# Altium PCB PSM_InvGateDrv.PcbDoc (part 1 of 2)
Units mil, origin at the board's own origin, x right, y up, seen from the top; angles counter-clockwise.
Board outline 5413.39 x 1771.65 mil, 2 copper layers (Top Layer, Bottom Layer), stack 62 mil thick; 130 components, 58 nets, 317 pads, 172 vias.
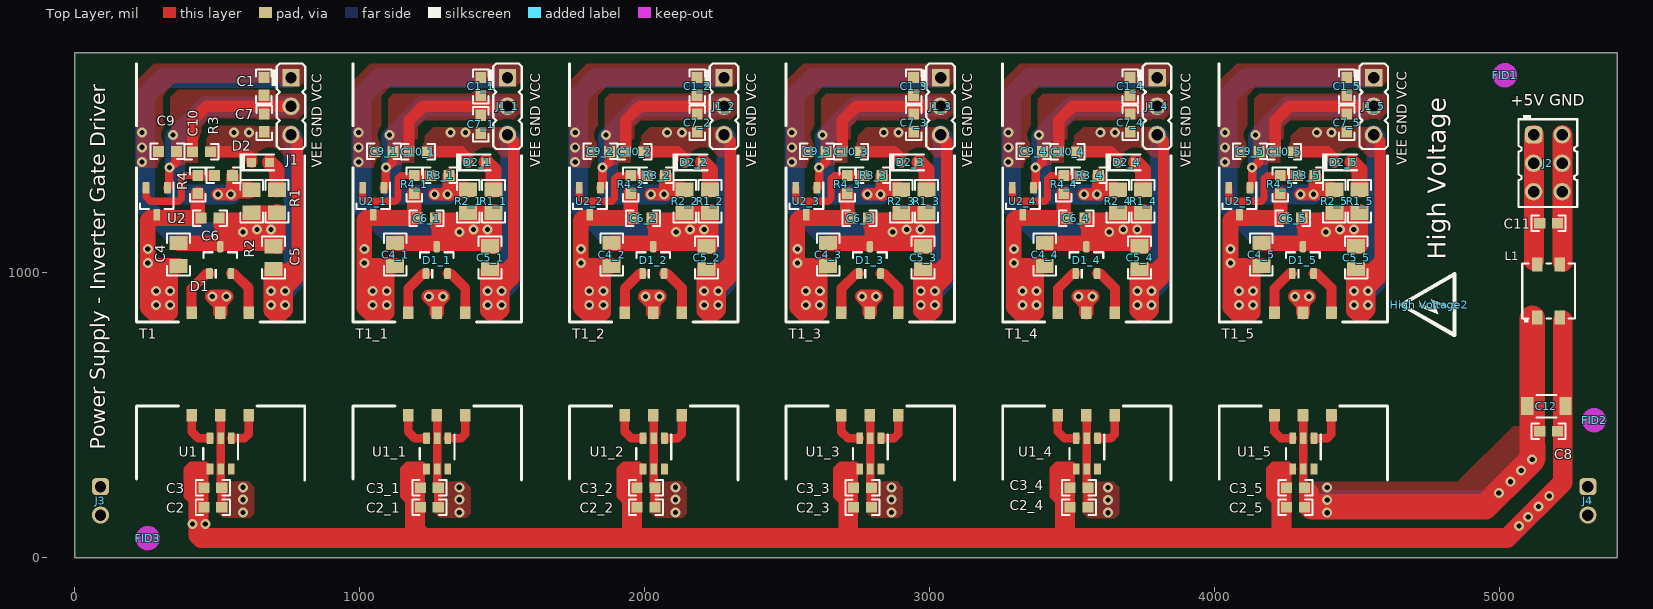
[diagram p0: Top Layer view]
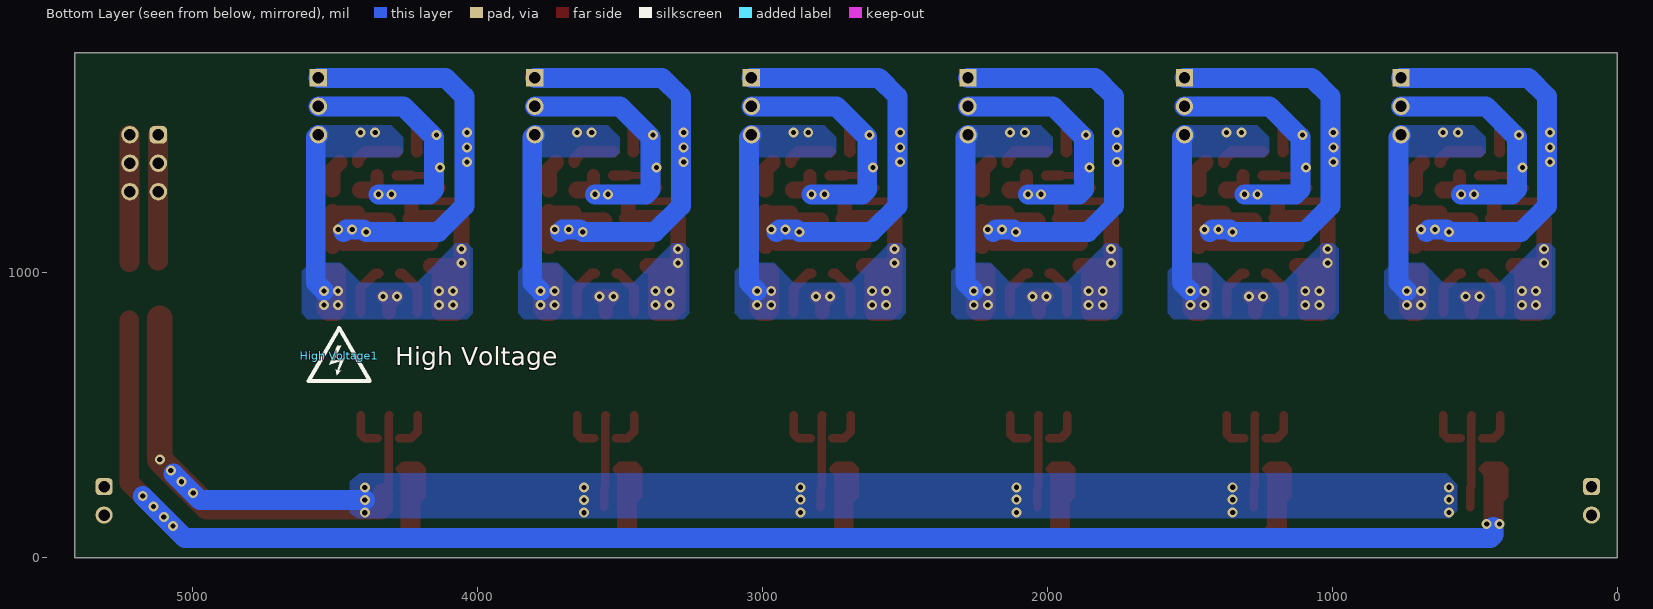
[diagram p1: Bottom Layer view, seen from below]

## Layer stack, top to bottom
Top Solder: solder mask 0.4, Solder Resist, Dk 3.5
Top Layer: signal copper 1.4
Dielectric1: core 59.2, FR-4, Dk 4.8
Bottom Layer: signal copper 1.4
Bottom Solder: solder mask 0.4, Solder Resist, Dk 3.5

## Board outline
0,0 5413.39,0 5413.39,1771.65 0,1771.65

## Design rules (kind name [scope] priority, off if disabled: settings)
AcuteAngle [All] p1: minimum=4.50000000000000E+0001 checktracksonly=FALSE
AssemblyTestPointUsage [All] p1: valid=2
BoardOutlineClearance BoardOutlineClearance_MountingHoles [OnCopper and InComponentClass('Mounting Holes')] p1: gap=20 ignorepadtopadclearanceinfootprint=FALSE
BoardOutlineClearance BoardOutlineClearance_Poly [OnCopper and IsPoly] p2: gap=25 ignorepadtopadclearanceinfootprint=FALSE
BoardOutlineClearance [OnCopper and Not InComponentClass('Logo') and not InComponentClass('FiducialMark') and not InRegion(1000,500,4000,800) and not InPoly] p3: gap=20 ignorepadtopadclearanceinfootprint=FALSE
Clearance Clearance_Keepouts [((IsTrack Or IsArc) And Not InPoly) And IsFree and IsKeepOut vs ((IsTrack Or IsArc) And Not InPoly) And IsFree and IsKeepOut] p1: gap=0 ignorepadtopadclearanceinfootprint=FALSE
Clearance Clearance_Poly [InPolygon] p2: gap=25 ignorepadtopadclearanceinfootprint=TRUE
Clearance Clearance_FiducialMark [IsKeepOut and InComponentClass('FiducialMark') vs IsPad and InComponentClass('FiducialMark')] p3: gap=0 ignorepadtopadclearanceinfootprint=FALSE
Clearance [All] p4: gap=7.87 ignorepadtopadclearanceinfootprint=TRUE
ComponentClearance ComponentClearance_MountingHoles_FiducialMarks [InComponentClass('Mounting Holes') vs InComponentClass('FiducialMark')] p1: gap=50 collisioncheckmode=3 verticalgap=10 showdistances=FALSE
ComponentClearance ComponentClearance_Shunt [InComponentClass('Header') vs InComponentClass('Shunt')] p2: gap=0 collisioncheckmode=3 verticalgap=0 showdistances=FALSE
ComponentClearance ComponentClearance_Logo [InComponentClass('Logo')] p3: gap=50 collisioncheckmode=3 verticalgap=10 showdistances=FALSE
ComponentClearance ComponentClearance_ScrewToNut [(HasFootprint('NY PMS 440 0025 PH')) vs (HasFootprint('Keystone_1902C'))] p4: gap=5 collisioncheckmode=3 verticalgap=10 showdistances=FALSE
ComponentClearance ComponentClearance_MountingHoles [InComponentClass('Mounting Holes')] p5: gap=250 collisioncheckmode=3 verticalgap=100000 showdistances=FALSE
ComponentClearance ComponentClearance_SmallPassives [HasFootprint('0201*') or HasFootprint('0402*') or HasFootprint('0508') or HasFootprint('0603*') or HasFootprint('0612') or HasFootprint('0805*') or HasFootprint('0815*') or HasFootprint('0830*') or HasFootprint('1206*') or HasFootprint('1210*') or HasFootprint('1808*') or HasFootprint('1812*') or HasFootprint('1825*') or HasFootprint('2010*') or HasFootprint('2220*') or HasFootprint('2225*') or HasFootprint('2512*') or HasFootprint('2728*') or HasFootprint('3518*') vs HasFootprint('0201*') or HasFootprint('0402*') or HasFootprint('0508') or HasFootprint('0603*') or HasFootprint('0612') or HasFootprint('0805*') or HasFootprint('0815*') or HasFootprint('0830*') or HasFootprint('1206*') or HasFootprint('1210*') or HasFootprint('1808*') or HasFootprint('1812*') or HasFootprint('1825*') or HasFootprint('2010*') or HasFootprint('2220*') or HasFootprint('2225*') or HasFootprint('2512*') or HasFootprint('2728*') or HasFootprint('3518*')] p6: gap=14.96 collisioncheckmode=3 verticalgap=10 showdistances=FALSE
ComponentClearance ComponentClearance_THtoSMT [IsThruComponent vs IsSMTComponent] p7: gap=25 collisioncheckmode=3 verticalgap=30 showdistances=FALSE
ComponentClearance ComponentClearance_THtoTH [IsThruComponent vs IsThruComponent] p8: gap=30 collisioncheckmode=3 verticalgap=30 showdistances=FALSE
ComponentClearance [All] p9: gap=30 collisioncheckmode=3 verticalgap=10 showdistances=FALSE
DiffPairsRouting [All] p1: maxlimit=100 minlimit=10 mostfreqgap=10 toplayer_minwidth=15 toplayer_maxwidth=15 toplayer_prefwidth=15 bottomlayer_minwidth=15 bottomlayer_maxwidth=15 bottomlayer_prefwidth=15 maxuncoupledlength=1000
FabricationTestPointUsage TestPointUsage [All] p1: valid=2 allowmultiple=FALSE
FabricationTestpoint Testpoint [All] p1: side=3 testpointundercomponent=TRUE minsize=40 maxsize=100 preferedsize=60 minholesize=0 maxholesize=40 preferedholesize=32 testpointgrid=1 allowsidetop=TRUE allowsidebottom=TRUE usegrid=TRUE gridtolerance=0.01
FanoutControl Fanout_LCC [IsLCC] p1: bgadir=Out bgaviamode=Centered fanoutstyle=Auto fanoutdirection=Alternating viagrid=1 // Fanout_LCC (Default Rule)
FanoutControl Fanout_BGA [IsBGA] p2: bgadir=Out bgaviamode=Centered fanoutstyle=Auto fanoutdirection=Alternating viagrid=1 // Fanout_BGA (Default Rule)
FanoutControl Fanout_Default [All] p4: bgadir=Out bgaviamode=Centered fanoutstyle=Auto fanoutdirection=Alternating viagrid=1 // Fanout_Default (Default Rule)
FanoutControl Fanout_Small [(CompPinCount < 5)] p5: bgadir=Out bgaviamode=Centered fanoutstyle=Auto fanoutdirection=OutThenIn viagrid=1 // Fanout_Small (Default Rule)
HoleSize [All] p1: absolutevalues=TRUE maxlimit=251 minlimit=7.87 maxpercent=80.000 minpercent=20.000
MinimumAnnularRing MinimumAnnularRing_ThermalPadVias [IsVia and InAnyComponent] p1: minimumring=5.91
MinimumAnnularRing [All] p2: minimumring=7.87
MinimumSolderMaskSliver MinimumSolderMaskSliver_Logo [InComponentClass('Logo') vs InComponentClass('Logo')] p1: minsoldermaskwidth=0.7
MinimumSolderMaskSliver [All] p2: minsoldermaskwidth=3.94
PlaneConnect [All] p1: planeconnectstyle=Relief reliefexpansion=10 reliefentries=4 reliefconductorwidth=10 reliefairgap=10
PolygonConnect [All] p1: connectstyle=Direct reliefconductorwidth=10 reliefentries=4 polygonreliefangle="90 Angle" airgapwidth=10
RoomDefinition "Bias Supply_4" [InComponentClass('Bias Supply')] p1: confinementstyle=ConfineIn formatcopy=TRUE lockcomponents=FALSE outline 4615.87,338.9 4615.87,1735.5 4015.87,1735.5 4015.87,338.9
RoomDefinition "Bias Supply_3" [InComponentClass('Bias Supply')] p2: confinementstyle=ConfineIn formatcopy=TRUE lockcomponents=FALSE outline 3855.87,338.9 3855.87,1735.5 3255.87,1735.5 3255.87,338.9
RoomDefinition "Bias Supply_2" [InComponentClass('Bias Supply')] p3: confinementstyle=ConfineIn formatcopy=TRUE lockcomponents=FALSE outline 3095.87,338.9 3095.87,1735.5 2495.87,1735.5 2495.87,338.9
RoomDefinition "Bias Supply_1" [InComponentClass('Bias Supply')] p4: confinementstyle=ConfineIn formatcopy=TRUE lockcomponents=FALSE outline 2335.87,338.9 2335.87,1735.5 1735.87,1735.5 1735.87,338.9
RoomDefinition 1 [InComponentClass('1')] p5: confinementstyle=ConfineIn formatcopy=TRUE lockcomponents=FALSE outline 4615.87,338.9 4615.87,1735.5 4015.87,1735.5 4015.87,338.9
RoomDefinition 2 [InComponentClass('2')] p6: confinementstyle=ConfineIn formatcopy=TRUE lockcomponents=FALSE outline 3855.87,338.9 3855.87,1735.5 3255.87,1735.5 3255.87,338.9
RoomDefinition 3 [InComponentClass('3')] p7: confinementstyle=ConfineIn formatcopy=TRUE lockcomponents=FALSE outline 3095.87,338.9 3095.87,1735.5 2495.87,1735.5 2495.87,338.9
RoomDefinition "Stark Gate Driver_1" [InComponentClass('Stark Gate Driver_1')] p8: confinementstyle=ConfineIn formatcopy=TRUE lockcomponents=FALSE outline 2335.87,338.9 2335.87,1735.5 1735.87,1735.5 1735.87,338.9
RoomDefinition "Bias Supply" [InComponentClass('Bias Supply')] p9: confinementstyle=ConfineIn formatcopy=TRUE lockcomponents=FALSE outline 815.87,338.9 815.87,1735.5 215.87,1735.5 215.87,338.9
RoomDefinition 5 [InComponentClass('5')] p10: confinementstyle=ConfineIn formatcopy=TRUE lockcomponents=FALSE outline 1575.87,338.9 1575.87,1735.5 975.87,1735.5 975.87,338.9
RoutingVias ThermalPadVias [IsVia and InAnyComponent] p1: holewidth=7.87 width=19.68 viastyle="Through Hole" minholewidth=7.87 minwidth=19.68 maxholewidth=12.99 maxwidth=23.62
RoutingVias [All] p2: holewidth=16 width=34 viastyle="Through Hole" minholewidth=7.87 minwidth=26 maxholewidth=40 maxwidth=65
SilkToBoardRegionClearance [Not ((IsComment or IsDesignator) And (Hide <> 'False')) and not InRegion(1000,500,4000,800)] p1:
SilkToSilkClearance SilkToSilkClearance_Pb-FreeLogo [(HasFootprint('Pb-Free_Overlay_Medium') OR HasFootprint('Pb-Free_Overlay_Small')) vs (HasFootprint('Pb-Free_Overlay_Medium') OR HasFootprint('Pb-Free_Overlay_Small'))] p1: silktosilkclearance=0
SilkToSilkClearance [All] p2: silktosilkclearance=2
SilkToSolderMaskClearance SilkToComponentPadClearance [(IsPad or IsFill or IsRegion) and InAnycomponent] p1: minsilkscreentomaskgap=0 clearancetoexposedcopper=TRUE
SilkToSolderMaskClearance "Silk to Solder Mask Opening" [All] p2: minsilkscreentomaskgap=1 clearancetoexposedcopper=FALSE
SolderMaskExpansion [All] p1: expansion=1.97
UnRoutedNet [All] p1: checkbadconnections=TRUE
Width [All] p1: maxlimit=100 minlimit=6 preferedwidth=10 checkconnectedcopper=TRUE
14 further rules are at their usual default settings.

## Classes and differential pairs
component class Header: J1 J1_1 J1_2 J1_3 J1_4 J1_5 J2 J3 J4
component class "Bias Supply": C1 C1_1 C1_2 C1_3 C1_4 C1_5 C2 C2_1 C2_2 C2_3 C2_4 C2_5 C3 C3_1 C3_2 C3_3 C3_4 C3_5 C4 C4_1 C4_2 C4_3 C4_4 C4_5 C5 C5_1 C5_2 C5_3 C5_4 C5_5 C6 C6_1 C6_2 C6_3 C6_4 C6_5 C7 C7_1 C7_2 C7_3 C7_4 C7_5 C8 C9 C9_1 C9_2 C9_3 C9_4 C9_5 C10 C10_1 C10_2 C10_3 C10_4 C10_5 C11 C12 D1 D1_1 D1_2 D1_3 D1_4 D1_5 D2 D2_1 D2_2 D2_3 D2_4 D2_5 J1 J1_1 J1_2 J1_3 J1_4 J1_5 J2 J3 J4 L1 R1 R1_1 R1_2 R1_3 R1_4 R1_5 R2 R2_1 R2_2 R2_3 R2_4 R2_5 R3 R3_1 R3_2 R3_3 R3_4 R3_5 R4 R4_1 R4_2 R4_3 R4_4 R4_5 T1 T1_1 T1_2 T1_3 T1_4 T1_5 U1 U1_1 U1_2 U1_3 U1_4 U1_5 U2 U2_1 U2_2 U2_3 U2_4 U2_5
component class Hardware: FID1 FID2 FID3 "High Voltage1" "High Voltage2" ZZ1 ZZ2 ZZ3 ZZ4
component class FiducialMark: FID1 FID2 FID3
component class AssemblyNote: ZZ1 ZZ2 ZZ3 ZZ4

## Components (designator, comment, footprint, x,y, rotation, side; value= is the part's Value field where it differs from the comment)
C1 "CGA3E2X7R1E104K080AA" 0603 663.75,1653.91 r270 top value=0.1uF
C1_1 "CGA3E2X7R1E104K080AA" 0603 1424.5,1653.54 r270 top value=0.1uF
C1_2 "CGA3E2X7R1E104K080AA" 0603 2183.75,1653.91 r270 top value=0.1uF
C1_3 "CGA3E2X7R1E104K080AA" 0603 2943.75,1653.91 r270 top value=0.1uF
C1_4 "CGA3E2X7R1E104K080AA" 0603 3703.75,1653.91 r270 top value=0.1uF
C1_5 "CGA3E2X7R1E104K080AA" 0603 4463.75,1653.91 r270 top value=0.1uF
C2 "GRT188C81A106ME13D" 0603 484.38,176.52 r180 top value=10uF
C2_1 "GRT188C81A106ME13D" 0603 1244.38,176.52 r180 top value=10uF
C2_2 "GRT188C81A106ME13D" 0603 2004.38,176.52 r180 top value=10uF
C2_3 "GRT188C81A106ME13D" 0603 2764.38,176.52 r180 top value=10uF
C2_4 "GRT188C81A106ME13D" 0603 3524.38,176.52 r180 top value=10uF
C2_5 "GRT188C81A106ME13D" 0603 4284.38,176.52 r180 top value=10uF
C3 "CGA3E2X7R1E104K080AA" 0603 484.38,245.42 r180 top value=0.1uF
C3_1 "CGA3E2X7R1E104K080AA" 0603 1244.38,245.42 r180 top value=0.1uF
C3_2 "CGA3E2X7R1E104K080AA" 0603 2004.38,245.42 r180 top value=0.1uF
C3_3 "CGA3E2X7R1E104K080AA" 0603 2764.38,245.42 r180 top value=0.1uF
C3_4 "CGA3E2X7R1E104K080AA" 0603 3524.38,245.42 r180 top value=0.1uF
C3_5 "CGA3E2X7R1E104K080AA" 0603 4284.38,245.42 r180 top value=0.1uF
C4 "GRT21BR61H475KE13L" 0805_HV 364.3,1063.78 r270 top value=4.7uF
C4_1 "GRT21BR61H475KE13L" 0805_HV 1124.3,1063.78 r270 top value=4.7uF
C4_2 "GRT21BR61H475KE13L" 0805_HV 1884.3,1063.78 r270 top value=4.7uF
C4_3 "GRT21BR61H475KE13L" 0805_HV 2644.3,1063.78 r270 top value=4.7uF
C4_4 "GRT21BR61H475KE13L" 0805_HV 3404.3,1063.78 r270 top value=4.7uF
C4_5 "GRT21BR61H475KE13L" 0805_HV 4164.3,1063.78 r270 top value=4.7uF
C5 "GRT21BR61H475KE13L" 0805_HV 697.3,1053.15 r270 top value=4.7uF
C5_1 "GRT21BR61H475KE13L" 0805_HV 1457.3,1053.15 r270 top value=4.7uF
C5_2 "GRT21BR61H475KE13L" 0805_HV 2217.3,1053.15 r270 top value=4.7uF
C5_3 "GRT21BR61H475KE13L" 0805_HV 2977.3,1053.15 r270 top value=4.7uF
C5_4 "GRT21BR61H475KE13L" 0805_HV 3737.3,1053.15 r270 top value=4.7uF
C5_5 "GRT21BR61H475KE13L" 0805_HV 4497.3,1053.15 r270 top value=4.7uF
C6 "CGA3E2X7R1E104K080AA" 0603 474.54,1191.73 r180 top value=0.1uF
C6_1 "CGA3E2X7R1E104K080AA" 0603 1234.54,1191.73 r180 top value=0.1uF
C6_2 "CGA3E2X7R1E104K080AA" 0603 1994.54,1191.73 r180 top value=0.1uF
C6_3 "CGA3E2X7R1E104K080AA" 0603 2754.54,1191.73 r180 top value=0.1uF
C6_4 "CGA3E2X7R1E104K080AA" 0603 3514.54,1191.73 r180 top value=0.1uF
C6_5 "CGA3E2X7R1E104K080AA" 0603 4274.54,1191.73 r180 top value=0.1uF
C7 "CGA3E2X7R1E104K080AA" 0603 664.5,1525.96 r270 top value=0.1uF
C7_1 "CGA3E2X7R1E104K080AA" 0603 1424.5,1520.96 r270 top value=0.1uF
C7_2 "CGA3E2X7R1E104K080AA" 0603 2184.5,1525.96 r270 top value=0.1uF
C7_3 "CGA3E2X7R1E104K080AA" 0603 2944.5,1525.96 r270 top value=0.1uF
C7_4 "CGA3E2X7R1E104K080AA" 0603 3704.5,1525.96 r270 top value=0.1uF
C7_5 "CGA3E2X7R1E104K080AA" 0603 4464.5,1525.96 r270 top value=0.1uF
C8 "CGA3E2X7R1E104K080AA" 0603 5172.8,442.91 r0 top value=0.1uF
C9 "CGA3E2X7R1E104K080AA" 0603 324.93,1425.54 r0 top value=0.1uF
C9_1 "CGA3E2X7R1E104K080AA" 0603 1084.93,1425.54 r0 top value=0.1uF
C9_2 "CGA3E2X7R1E104K080AA" 0603 1844.93,1425.54 r0 top value=0.1uF
C9_3 "CGA3E2X7R1E104K080AA" 0603 2604.93,1425.54 r0 top value=0.1uF
C9_4 "CGA3E2X7R1E104K080AA" 0603 3364.93,1425.54 r0 top value=0.1uF
C9_5 "CGA3E2X7R1E104K080AA" 0603 4124.93,1425.54 r0 top value=0.1uF
C10 "CGA3E2X7R1E104K080AA" 0603 444.52,1424.55 r0 top value=0.1uF
C10_1 "CGA3E2X7R1E104K080AA" 0603 1204.52,1424.55 r0 top value=0.1uF
C10_2 "CGA3E2X7R1E104K080AA" 0603 1964.52,1424.55 r0 top value=0.1uF
C10_3 "CGA3E2X7R1E104K080AA" 0603 2724.52,1424.55 r0 top value=0.1uF
C10_4 "CGA3E2X7R1E104K080AA" 0603 3484.52,1424.55 r0 top value=0.1uF
C10_5 "CGA3E2X7R1E104K080AA" 0603 4244.52,1424.55 r0 top value=0.1uF
C11 "GRT188R61C475KE13D" 0603 5172.8,1173.03 r0 top value=4.7uF
C12 "GRJ31CR71A226KE12L" 1206_190 5164.92,531.5 r0 top value=22uF
D1 "BAV70-E3-08" SOT-23 510.26,1044.09 r90 top value=70V
D1_1 "BAV70-E3-08" SOT-23 1270.26,1044.09 r90 top value=70V
D1_2 "BAV70-E3-08" SOT-23 2030.26,1044.09 r90 top value=70V
D1_3 "BAV70-E3-08" SOT-23 2790.26,1044.09 r90 top value=70V
D1_4 "BAV70-E3-08" SOT-23 3550.26,1044.09 r90 top value=70V
D1_5 "BAV70-E3-08" SOT-23 4310.26,1044.09 r90 top value=70V
D2 "150060GS75000" WL-SMCW_GREEN 652.09,1387.15 r0 top value=Green
D2_1 "150060GS75000" WL-SMCW_GREEN 1412.09,1387.15 r0 top value=Green
D2_2 "150060GS75000" WL-SMCW_GREEN 2172.09,1387.15 r0 top value=Green
D2_3 "150060GS75000" WL-SMCW_GREEN 2932.09,1387.15 r0 top value=Green
D2_4 "150060GS75000" WL-SMCW_GREEN 3692.09,1387.15 r0 top value=Green
D2_5 "150060GS75000" WL-SMCW_GREEN 4452.09,1387.15 r0 top value=Green
FID1 "Fiducial" Fiducial10-20 5019.69,1692.91 r0 top
FID2 "Fiducial" Fiducial10-20 5332.48,482.28 r0 top
FID3 "Fiducial" Fiducial10-20 256.03,68.41 r0 top
"High Voltage1" "DANGER HIGH VOLTAGE" IEC_HighVoltage_Small 4485.56,708.66 r180 bottom
"High Voltage2" "DANGER HIGH VOLTAGE" IEC_HighVoltage_Small 4753.94,888.29 r90 top
J1 "GBC03SAAN" Sullins_Gxx03SAAN 758.63,1584 r270 top
J1_1 "GBC03SAAN" Sullins_Gxx03SAAN 1518.63,1584 r270 top
J1_2 "GBC03SAAN" Sullins_Gxx03SAAN 2278.63,1584 r270 top
J1_3 "GBC03SAAN" Sullins_Gxx03SAAN 3038.63,1584 r270 top
J1_4 "GBC03SAAN" Sullins_Gxx03SAAN 3798.63,1584 r270 top
J1_5 "GBC03SAAN" Sullins_Gxx03SAAN 4558.63,1584 r270 top
J2 "HTSW-103-07-G-D" Samtec_HTSW-103-07-x-D 5170.2,1384.27 r0 top
J3 "TSW-102-23-T-S" Samtec_TSW-102-23-X-S 90,199.27 r270 top
J4 "TSW-102-23-T-S" Samtec_TSW-102-23-X-S 5310.8,199.27 r270 top
L1 "ACM4520V-142-2P-T00" TDK_ACM4520 5172.8,935.83 r90 top
R1 "CRCW080519K1FKEA" 0805_HV 709.18,1250.79 r270 top value=19.1k
R1_1 "CRCW080519K1FKEA" 0805_HV 1469.18,1250.79 r270 top value=19.1k
R1_2 "CRCW080519K1FKEA" 0805_HV 2229.18,1250.79 r270 top value=19.1k
R1_3 "CRCW080519K1FKEA" 0805_HV 2989.18,1250.79 r270 top value=19.1k
R1_4 "CRCW080519K1FKEA" 0805_HV 3749.18,1250.79 r270 top value=19.1k
R1_5 "CRCW080519K1FKEA" 0805_HV 4509.18,1250.79 r270 top value=19.1k
R2 "ERJ-P06F4701V" 0805_HV 620.6,1250.79 r270 top value=4.70k
R2_1 "ERJ-P06F4701V" 0805_HV 1380.6,1250.79 r270 top value=4.70k
R2_2 "ERJ-P06F4701V" 0805_HV 2140.6,1250.79 r270 top value=4.70k
R2_3 "ERJ-P06F4701V" 0805_HV 2900.6,1250.79 r270 top value=4.70k
R2_4 "ERJ-P06F4701V" 0805_HV 3660.6,1250.79 r270 top value=4.70k
R2_5 "ERJ-P06F4701V" 0805_HV 4420.6,1250.79 r270 top value=4.70k
R3 "RT0603DRE073K01L" 0603 521.78,1341.34 r0 top value=3.01k
R3_1 "RT0603DRE073K01L" 0603 1281.78,1341.34 r0 top value=3.01k
R3_2 "RT0603DRE073K01L" 0603 2041.78,1341.34 r0 top value=3.01k
R3_3 "RT0603DRE073K01L" 0603 2801.78,1341.34 r0 top value=3.01k
R3_4 "RT0603DRE073K01L" 0603 3561.78,1341.34 r0 top value=3.01k
R3_5 "RT0603DRE073K01L" 0603 4321.78,1341.34 r0 top value=3.01k
R4 "RT0603DRE074K99L" 0603 431.33,1309.84 r90 top value=4.99k
R4_1 "RT0603DRE074K99L" 0603 1191.33,1309.84 r90 top value=4.99k
R4_2 "RT0603DRE074K99L" 0603 1951.33,1309.84 r90 top value=4.99k
R4_3 "RT0603DRE074K99L" 0603 2711.33,1309.84 r90 top value=4.99k
R4_4 "RT0603DRE074K99L" 0603 3471.33,1309.84 r90 top value=4.99k
R4_5 "RT0603DRE074K99L" 0603 4231.33,1309.84 r90 top value=4.99k
T1 "750317722" Wurth_750317722 510.26,679.92 r90 top
T1_1 "750317722" Wurth_750317722 1270.26,679.92 r90 top
T1_2 "750317722" Wurth_750317722 2030.26,679.92 r90 top
T1_3 "750317722" Wurth_750317722 2790.26,679.92 r90 top
T1_4 "750317722" Wurth_750317722 3550.26,679.92 r90 top
T1_5 "750317722" Wurth_750317722 4310.26,679.92 r90 top
U1 "SN6505DQDBVRQ1" DBV0006A_N 511.94,364.96 r270 top
U1_1 "SN6505DQDBVRQ1" DBV0006A_N 1271.94,364.96 r270 top
U1_2 "SN6505DQDBVRQ1" DBV0006A_N 2031.94,364.96 r270 top
U1_3 "SN6505DQDBVRQ1" DBV0006A_N 2791.94,364.96 r270 top
U1_4 "SN6505DQDBVRQ1" DBV0006A_N 3551.94,364.96 r270 top
U1_5 "SN6505DQDBVRQ1" DBV0006A_N 4311.94,364.96 r270 top
U2 "TL431AQDBZRQ1" DBZ0003A_N 287.53,1250.79 r270 top
U2_1 "TL431AQDBZRQ1" DBZ0003A_N 1047.53,1250.79 r270 top
U2_2 "TL431AQDBZRQ1" DBZ0003A_N 1807.53,1250.79 r270 top
U2_3 "TL431AQDBZRQ1" DBZ0003A_N 2567.53,1250.79 r270 top
U2_4 "TL431AQDBZRQ1" DBZ0003A_N 3327.53,1250.79 r270 top
U2_5 "TL431AQDBZRQ1" DBZ0003A_N 4087.53,1250.79 r270 top
ZZ1 "This Assembly Note is for PCB labels only" AssemblyNoteLabel 185,3946.41 r0 top
ZZ2 "These assemblies are ESD sensitive, ESD precautions shall be observed." AssemblyNote 187.81,3849.33 r0 top
ZZ3 "These assemblies must be clean and free from flux and all contaminants. Use of no clean flux is not acceptable." AssemblyNote 187.81,3760.78 r0 top
ZZ4 "These assemblies must comply with workmanship standards IPC-A-610 Class 2, unless otherwise specified." AssemblyNote 187.81,3672.22 r0 top

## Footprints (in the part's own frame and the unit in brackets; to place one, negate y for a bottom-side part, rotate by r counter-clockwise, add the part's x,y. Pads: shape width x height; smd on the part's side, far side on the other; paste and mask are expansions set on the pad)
0603 [mm] "0603 from SM-752 data"
  rect 1x0.95 smd: 1(-0.8,0) 2(0.8,0)
  silkscreen extent -1.52,-0.69 1.52,0.69, body extent -0.87,-0.47 0.87,0.47, height 1
0805_HV [mil] "0805 with 30mil clearance between pads"
  rect 50x63 smd: 1(-40,0) 2(40,0)
  silkscreen extent -74,-40 74,40, body extent -43,-29 43,29, height 57
1206_190 [mm] "1206_190"
  rect 1.1x1.6 smd: 1(-1.7,0) 2(1.7,0)
  silkscreen extent -0.9,-1 0.9,1, body extent -1.75,-0.95 1.75,0.95, height 1.9
AssemblyNote [mil] "Assembly Note"
AssemblyNoteLabel [mil] "Assembly Note for PCB Labels"
DBV0006A_N [mm] "SOT23, 6-Leads, Body 2.9x1.6mm, Pitch 0.95mm, Lead Span 2.8mm, IPC Medium Density"
  rrect17% 1x0.6 smd: 1(-1.375,0.95) 2(-1.375,0) 3(-1.375,-0.95) 4(1.375,-0.95) 5(1.375,0) 6(1.375,0.95)
  silkscreen extent -1.68,-1.55 0.5,1.55, body extent -1.42,-1.46 1.42,1.46, height 1.12
DBZ0003A_N [mm] "SOT23, 3-Leads, Body 2.9x1.3mm, Pitch 0.95mm, Lead Span 2.4mm, IPC Medium Density"
  rrect17% 1x0.6 smd: 1(-1.2,0.95) 2(-1.2,-0.95) 3(1.2,0)
  silkscreen extent -1.65,-1.5 0.7,1.5, body extent -1.26,-1.46 1.26,1.46, height 0.98
Fiducial10-20 [mm]
  round 1 smd mask+0.5: 1(0,0)
  Top Layer keep-out circle w1.178: c0,0 r0.5
IEC_HighVoltage_Small [mil]
  silkscreen extent -107,-88 107,97
Samtec_HTSW-103-07-x-D [mm] "Header, 2.54mm, 3x2, Gold, TH"
  rrect50% 1.55x1.55 hole 1.02: 1(-1.27,2.54)
  round 1.55 hole 1.02: 2(1.27,2.54) 3(-1.27,0) 4(1.27,0) 5(-1.27,-2.54) 6(1.27,-2.54)
  silkscreen extent -2.61,-3.91 2.61,4.3, body extent -2.51,-3.81 2.51,3.81, height 8.38
Samtec_TSW-102-23-X-S [mm] "Header, 2.54mm, 2x1, TH"
  rrect50% 1.53x1.53 hole 1.02: 1(-1.27,0)
  round 1.53 hole 1.02: 2(1.27,0)
  body extent -2.67,-1.27 2.54,1.27, height 8.38
SOT-23 [mm] "SOT23, 3-Leads, Body 2.9x1.3mm, Pitch 0.95mm, Lead Span 2.5mm, IPC Medium Density"
  rrect50% 1x0.6 smd: 1(-1.2,0.95) 2(-1.2,-0.95) 3(1.2,0)
  silkscreen extent -1.62,-1.5 0.7,1.5, body extent -1.16,-1.45 1.21,1.45, height 1
Sullins_Gxx03SAAN [mm] "Header, 2.54 mm, 3x1, TH"
  rect 1.55x1.55 hole 1.016: 1(-2.54,0)
  round 1.55 hole 1.016: 2(0,0) 3(2.54,0)
  silkscreen extent -3.81,-1.75 3.81,1.27, body extent -3.81,-1.27 3.81,1.27, height 8.38
TDK_ACM4520 [mm] "SMD, 4-Leads, Body 4.7x4.5mm"
  rect 1.25x0.95 smd: 1(-2.375,1) 2(-2.375,-1) 3(2.375,-1) 4(2.375,1)
  silkscreen extent -2.8,-2.35 2.45,2.35, body extent -2.45,-2.35 2.45,2.35, height 2
WL-SMCW_GREEN [mm] "WURTH"
  rect 0.8x0.8 smd: 1(-0.8,0) 2(0.8,0)
  silkscreen extent -1.9,-0.8 1.2,0.8, body extent -0.85,-0.45 0.85,0.45, height 0.8
Wurth_750317722 [mm] "SMD, 6-Leads, Body 7.14x6.73mm, Pitch 2.54mm"
  rrect10% 1.12x0.96 smd: 1(-4.57,2.54) 2(-4.57,0) 3(-4.57,-2.54) 4(4.57,-2.54) 5(4.57,0) 6(4.57,2.54)
  body extent -5.23,-3.36 5.23,3.37, height 4.19

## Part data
C1 C1_1 C1_2 C1_3 C1_4 C1_5 C3 C3_1 C3_2 C3_3 C3_4 C3_5 C6 C6_1 C6_2 C6_3 C6_4 C6_5 C7 C7_1 C7_2 C7_3 C7_4 C7_5 C8 C9 C9_1 C9_2 C9_3 C9_4 C9_5 C10 C10_1 C10_2 C10_3 C10_4 C10_5: "CAP, CERM, 0.1 μF, 25 V,+/- 10%, X7R, AEC-Q200 Grade 1, 0603", Cap_Case=0603, Manufacturer=TDK, Supplier Part Number 1=445-5667-1-ND, TempCo=X7R, Tolerance_%=10, Value2=25V, ValueDisplayed=0.1μF
C2 C2_1 C2_2 C2_3 C2_4 C2_5: "CAP, CERM, 10 μF, 10 V,+/- 20%, X6S, AEC-Q200 Grade 2, 0603", Cap_Case=0603, Manufacturer=MuRata, Supplier Part Number 1=490-12283-1-ND, TempCo=X6S, Tolerance_%=20, Value2=10V, ValueDisplayed=10μF
C4 C4_1 C4_2 C4_3 C4_4 C4_5 C5 C5_1 C5_2 C5_3 C5_4 C5_5: "CAP, CERM, 4.7 μF, 50 V,+/- 10%, X5R, AEC-Q200 Grade 3, 0805", Cap_Case=0805, Manufacturer=MuRata, Supplier Part Number 1=490-12394-1-ND, TempCo=X5R, Tolerance_%=10, Value2=50V, ValueDisplayed=4.7μF
C11: library part CMP-0081052-1, "CAP, CERM, 4.7 μF, 16 V,+/- 10%, X5R, AEC-Q200 Grade 3, 0603", Cap_Case=0603, Manufacturer=MuRata, Supplier Part Number 1=490-12319-1-ND, TempCo=X5R, Tolerance_%=10%, Value2=16V, ValueDisplayed=4.7μF
C12: library part CMP-0074691-1, "CAP, CERM, 22 μF, 10 V,+/- 10%, X7R, 1206", Cap_Case=1206, Manufacturer=MuRata, Supplier Part Number 1=490-10937-1-ND, TempCo=X7R, Tolerance_%=10%, Value2=10V, ValueDisplayed=22μF
D1 D1_1 D1_2 D1_3 D1_4 D1_5: "Diode, Switching, 70 V, 0.25 A, AEC-Q101, SOT-23", Manufacturer=Vishay-Semiconductor, Supplier Part Number 1=BAV70-E3-08CT-ND, Value1=0.25A, Value2=1.25V
D2 D2_1 D2_2 D2_3 D2_4 D2_5: library part CMP-0002905-2, "LED, Green, SMD", Color=Green, Manufacturer="Wurth Elektronik", Value1=W, Value2=3.2V
FID1 FID2 FID3: library part CMP-0077181-1, "Fiducial mark.  There is nothing to buy or mount.", Manufacturer=N/A
"High Voltage1" "High Voltage2": library part CMP-0074835-1, "IEC 61010-1 High Voltage Warning"
J1 J1_1 J1_2 J1_3 J1_4 J1_5: library part CMP-0054577-1, "Header, 2.54 mm, 3x1, Gold, TH", Manufacturer="Sullins Connector Solutions"
J2: library part CMP-0055587-2, "Header, 2.54mm, 3x2, Gold, TH", Color=Natural, Manufacturer=Samtec, Supplier Part Number 1=HTSW-103-07-G-D-ND
J3 J4: library part CMP-0084558-1, "Header, 2.54mm, 2x1, Tin, TH", Color=Black, Current_A=6.3A, Manufacturer=Samtec, Voltage_V=550V
L1: library part CMP-0084502-1, "Coupled inductor,  ohm, AEC-Q200 Grade 1, SMD", Manufacturer=TDK
R1 R1_1 R1_2 R1_3 R1_4 R1_5: "RES, 19.1 k, 1%, 0.125 W, 0805", Manufacturer=Vishay-Dale, Power_W=0.125, Supplier Part Number 1=541-19.1KCCT-ND, TempCo="100 ppm/C", Tolerance_%=1, Value1=1%, Value2=0.125W, Value_Code=19k1, ValueDisplayed=19.1k
R2 R2_1 R2_2 R2_3 R2_4 R2_5: library part CMP-0021852-2, "RES, 4.70 k, 1%, 0.5 W, AEC-Q200 Grade 0, 0805", Manufacturer=Panasonic, Power_W=500mW, Supplier Part Number 1=P16073CT-ND, TempCo="100 ppm/C", Tolerance_%=1%, Value2=0.5W, Value_Code=4k70, ValueDisplayed=4.70k
R3 R3_1 R3_2 R3_3 R3_4 R3_5: "RES, 3.01 k, 0.5%, 0.1 W, 0603", Manufacturer="Yageo America", Power_W=0.1, TempCo="50 ppm/C", Tolerance_%=0.5, Value1=0.5%, Value2=0.1W, Value_Code=3k01, ValueDisplayed=3.01k
R4 R4_1 R4_2 R4_3 R4_4 R4_5: "RES, 4.99 k, 0.5%, 0.1 W, 0603", Manufacturer="Yageo America", Power_W=0.1, TempCo="50 ppm/C", Tolerance_%=0.5, Value1=0.5%, Value2=0.1W, Value_Code=4k99, ValueDisplayed=4.99k
T1 T1_1 T1_2 T1_3 T1_4 T1_5: library part CMP-0081994-1, "Transformer, 320 uH, SMD", Manufacturer="Wurth Elektronik"
U1 U1_1 U1_2 U1_3 U1_4 U1_5: library part CMP-0860735-1, "SN6505DQDBVRQ1, DBV0006A (SOT-23-6)", Alternate Manufacturer="Texas Instruments", Alternate PartNumber=SN6505DQDBVTQ1
U2 U2_1 U2_2 U2_3 U2_4 U2_5: "Automotive Catalog Adjustable Precision Shunt Regulator, 34 ppm / degC, 100 mA, -40 to 125 degC, 3-pin SOT-23 (DBZ), Green (RoHS & no Sb/Br)", Alternate Manufacturer="Texas Instruments", Alternate PartNumber=Equivalent, Rating=Automotive, Supplier Part Number 1=296-21853-2-ND, Temp Coeff(Typ)(ppm/ degree C)=34
ZZ1: library part CMP-0003616-3
ZZ2: library part CMP-0077236-1
ZZ3: library part CMP-0077237-1
ZZ4: library part CMP-0077238-1

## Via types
v1: diameter 35, hole 18, Top Layer to Bottom Layer, 172 vias

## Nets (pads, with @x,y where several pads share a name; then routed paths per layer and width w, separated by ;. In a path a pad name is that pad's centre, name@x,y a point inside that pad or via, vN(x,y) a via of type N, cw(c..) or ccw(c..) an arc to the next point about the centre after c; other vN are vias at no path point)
5Vin: C11.1 J2.1 J2.3 J2.5 L1.4 | length 442
  Top Layer w70: L1.4@5120.8,1041.95 5120.8,1284 5120.8,1384 J2.1@5120.8,1484
5Vs: C2.1 C2_1.1 C2_2.1 C2_3.1 C2_4.1 C2_5.1 C3.1 C3_1.1 C3_2.1 C3_3.1 C3_4.1 C3_5.1 C8.1 C12.1 L1.1 T1.2 T1_1.2 T1_2.2 T1_3.2 T1_4.2 T1_5.2 U1.2 U1.5 U1_1.2 U1_1.5 U1_2.2 U1_2.5 U1_3.2 U1_3.5 U1_4.2 U1_4.5 U1_5.2 U1_5.5 | length 4047.4
  Top Layer w30: T1.2@510.26,500 511.94,498.33 U1.2@511.94,419.09 U1.5@511.94,310.83 511.94,249.35 C3.1@515.87,245.42 C2.1@515.87,176.52 ; T1_1.2@1270.26,500 1271.94,498.33 U1_1.2@1271.94,419.09 U1_1.5@1271.94,310.83 1271.94,249.35 C3_1.1@1275.87,245.42 C2_1.1@1275.87,176.52 ; T1_2.2@2030.26,500 2031.94,498.33 U1_2.2@2031.94,419.09 U1_2.5@2031.94,310.83 2031.94,249.35 C3_2.1@2035.87,245.42 C2_2.1@2035.87,176.52 ; T1_3.2@2790.26,500 2791.94,498.33 U1_3.2@2791.94,419.09 U1_3.5@2791.94,310.83 2791.94,249.35 C3_3.1@2795.87,245.42 C2_3.1@2795.87,176.52 ; T1_4.2@3550.26,500 3551.94,498.33 U1_4.2@3551.94,419.09 U1_4.5@3551.94,310.83 3551.94,249.35 C3_4.1@3555.87,245.42 C2_4.1@3555.87,176.52 ; T1_5.2@4310.26,500 4311.94,498.33 U1_5.2@4311.94,419.09 U1_5.5@4311.94,310.83 4311.94,249.35 C3_5.1@4315.87,245.42 C2_5.1@4315.87,176.52
  Top Layer w70: 4331.62,226.38 4331.62,189.22 4341.77,179.08
  Top Layer w90: 4341.77,179.08 4950.54,179.08 4968.31,196.85 v1(4997.83,226.38) 5027.36,255.91 5055.41,283.95 v1(5115.16,343.7) L1.1@5115.16,839.37
  Bottom Layer w70: v1(4395.6,201.85) 4968.31,201.85 ; 4974.79,201.85 v1@5067.47,294.54
  other v1: 3625.83,157.48 4395.6,157.48 590.55,158.87 1349.37,158.87 2108.19,158.87 2867.01,158.87 3625.83,201.85 590.55,203.24 1349.37,203.24 2108.19,203.24 2867.01,203.24 3625.83,245.42 4395.6,245.42 590.55,246.81 1349.37,246.81 2108.19,246.81 2867.01,246.81 5039.37,266.43 5076.57,305.12
+15V_1: C1.1 C4.1 C5.1 C6.1 C9.1 D1.3 J1.1 R1.2 R2.2 | length 2400.9
  Top Layer w50: R2.2@620.6,1210.79 689.1,1210.79 R1.2@698.94,1200.94
  Top Layer w55: C4.1@364.3,1103.78 C5.1@669.42,1103.78
  Top Layer w60: C6.1@515.87,1181.89 515.87,1168.11 ; 521.78,1133.31 521.78,1162.2 ; R1.2@698.94,1200.94 679.89,1181.89 ; C5.1@709.18,1095.98 R1.2@709.18,1210.79 ; 515.87,1168.11 529.65,1181.89 679.89,1181.89 ; 515.87,1168.11 521.78,1162.2 ; 521.78,1162.2 550.68,1133.31 698.94,1133.31 680.68,1151.57 v1(688.98,1151.57) 688.98,1171.29 679.13,1181.13 679.26,1181.26 679.89,1181.89
  Bottom Layer w70: 669.88,1142.52 660.83,1151.57 v1(639.76,1151.57) 599.73,1151.57 v1(590.68,1142.52) 337.72,1142.52 246.19,1234.06 246.19,1618.02 312.17,1684 J1.1@758.63,1684
  other v1: 236.35,1388.58 236.35,1440.1 236.35,1492.02
+15V_2: C1_1.1 C4_1.1 C5_1.1 C6_1.1 C9_1.1 D1_1.3 J1_1.1 R1_1.2 R2_1.2 | length 2400.9
  Top Layer w50: R2_1.2@1380.6,1210.79 1449.1,1210.79 R1_1.2@1458.94,1200.94
  Top Layer w55: C4_1.1@1124.3,1103.78 C5_1.1@1429.42,1103.78
  Top Layer w60: C6_1.1@1275.87,1181.89 1275.87,1168.11 ; 1281.78,1133.31 1281.78,1162.2 ; R1_1.2@1458.94,1200.94 1439.89,1181.89 ; C5_1.1@1469.18,1095.98 R1_1.2@1469.18,1210.79 ; 1275.87,1168.11 1281.78,1162.2 ; 1275.87,1168.11 1289.65,1181.89 1439.89,1181.89 ; 1281.78,1162.2 1310.68,1133.31 1458.94,1133.31 1440.68,1151.57 v1(1448.98,1151.57) 1448.98,1171.29 1439.13,1181.13 1439.26,1181.26 1439.89,1181.89
  Bottom Layer w70: 1429.88,1142.52 1420.83,1151.57 v1(1399.76,1151.57) 1359.73,1151.57 v1(1350.68,1142.52) 1097.72,1142.52 1006.19,1234.06 1006.19,1618.02 1072.17,1684 J1_1.1@1518.63,1684
  other v1: 996.35,1388.58 996.35,1440.1 996.35,1492.02
+15V_3: C1_2.1 C4_2.1 C5_2.1 C6_2.1 C9_2.1 D1_2.3 J1_2.1 R1_2.2 R2_2.2 | length 2400.9
  Top Layer w50: R2_2.2@2140.6,1210.79 2209.1,1210.79 R1_2.2@2218.94,1200.94
  Top Layer w55: C4_2.1@1884.3,1103.78 C5_2.1@2189.42,1103.78
  Top Layer w60: C6_2.1@2035.87,1181.89 2035.87,1168.11 ; 2041.78,1133.31 2041.78,1162.2 ; R1_2.2@2218.94,1200.94 2199.89,1181.89 ; C5_2.1@2229.18,1095.98 R1_2.2@2229.18,1210.79 ; 2035.87,1168.11 2041.78,1162.2 ; 2035.87,1168.11 2049.65,1181.89 2199.89,1181.89 ; 2041.78,1162.2 2070.68,1133.31 2218.94,1133.31 2200.68,1151.57 v1(2208.98,1151.57) 2208.98,1171.29 2199.13,1181.13 2199.26,1181.26 2199.89,1181.89
  Bottom Layer w70: 2189.88,1142.52 2180.83,1151.57 v1(2159.76,1151.57) 2119.73,1151.57 v1(2110.68,1142.52) 1857.72,1142.52 1766.19,1234.06 1766.19,1618.02 1832.17,1684 J1_2.1@2278.63,1684
  other v1: 1756.35,1388.58 1756.35,1440.1 1756.35,1492.02
+15V_4: C1_3.1 C4_3.1 C5_3.1 C6_3.1 C9_3.1 D1_3.3 J1_3.1 R1_3.2 R2_3.2 | length 2400.9
  Top Layer w50: R2_3.2@2900.6,1210.79 2969.1,1210.79 R1_3.2@2978.94,1200.94
  Top Layer w55: C4_3.1@2644.3,1103.78 C5_3.1@2949.42,1103.78
  Top Layer w60: C6_3.1@2795.87,1181.89 2795.87,1168.11 ; 2801.78,1133.31 2801.78,1162.2 ; R1_3.2@2978.94,1200.94 2959.89,1181.89 ; C5_3.1@2989.18,1095.98 R1_3.2@2989.18,1210.79 ; 2795.87,1168.11 2801.78,1162.2 ; 2795.87,1168.11 2809.65,1181.89 2959.89,1181.89 ; 2801.78,1162.2 2830.68,1133.31 2978.94,1133.31 2960.68,1151.57 v1(2968.98,1151.57) 2968.98,1171.29 2959.13,1181.13 2959.26,1181.26 2959.89,1181.89
  Bottom Layer w70: 2949.88,1142.52 2940.83,1151.57 v1(2919.76,1151.57) 2879.73,1151.57 v1(2870.68,1142.52) 2617.72,1142.52 2526.19,1234.06 2526.19,1618.02 2592.17,1684 J1_3.1@3038.63,1684
  other v1: 2516.35,1388.58 2516.35,1440.1 2516.35,1492.02
+15V_5: C1_4.1 C4_4.1 C5_4.1 C6_4.1 C9_4.1 D1_4.3 J1_4.1 R1_4.2 R2_4.2 | length 2400.9
  Top Layer w50: R2_4.2@3660.6,1210.79 3729.1,1210.79 R1_4.2@3738.94,1200.94
  Top Layer w55: C4_4.1@3404.3,1103.78 C5_4.1@3709.42,1103.78
  Top Layer w60: C6_4.1@3555.87,1181.89 3555.87,1168.11 ; 3561.78,1133.31 3561.78,1162.2 ; R1_4.2@3738.94,1200.94 3719.89,1181.89 ; C5_4.1@3749.18,1095.98 R1_4.2@3749.18,1210.79 ; 3555.87,1168.11 3561.78,1162.2 ; 3555.87,1168.11 3569.65,1181.89 3719.89,1181.89 ; 3561.78,1162.2 3590.68,1133.31 3738.94,1133.31 3720.68,1151.57 v1(3728.98,1151.57) 3728.98,1171.29 3719.13,1181.13 3719.26,1181.26 3719.89,1181.89
  Bottom Layer w70: 3709.88,1142.52 3700.83,1151.57 v1(3679.76,1151.57) 3639.73,1151.57 v1(3630.68,1142.52) 3377.72,1142.52 3286.19,1234.06 3286.19,1618.02 3352.17,1684 J1_4.1@3798.63,1684
  other v1: 3276.35,1388.58 3276.35,1440.1 3276.35,1492.02
+15V_6: C1_5.1 C4_5.1 C5_5.1 C6_5.1 C9_5.1 D1_5.3 J1_5.1 R1_5.2 R2_5.2 | length 2400.9
  Top Layer w50: R2_5.2@4420.6,1210.79 4489.1,1210.79 R1_5.2@4498.94,1200.94
  Top Layer w55: C4_5.1@4164.3,1103.78 C5_5.1@4469.42,1103.78
  Top Layer w60: C6_5.1@4315.87,1181.89 4315.87,1168.11 ; 4321.78,1133.31 4321.78,1162.2 ; R1_5.2@4498.94,1200.94 4479.89,1181.89 ; C5_5.1@4509.18,1095.98 R1_5.2@4509.18,1210.79 ; 4315.87,1168.11 4321.78,1162.2 ; 4315.87,1168.11 4329.65,1181.89 4479.89,1181.89 ; 4321.78,1162.2 4350.68,1133.31 4498.94,1133.31 4480.68,1151.57 v1(4488.98,1151.57) 4488.98,1171.29 4479.13,1181.13 4479.26,1181.26 4479.89,1181.89
  Bottom Layer w70: 4469.88,1142.52 4460.83,1151.57 v1(4439.76,1151.57) 4399.73,1151.57 v1(4390.68,1142.52) 4137.72,1142.52 4046.19,1234.06 4046.19,1618.02 4112.17,1684 J1_5.1@4558.63,1684
  other v1: 4036.35,1388.58 4036.35,1440.1 4036.35,1492.02
-4V_1: C4.2 C5.2 C6.2 C7.2 C10.2 D2.1 J1.3 R4.1 T1.5 U2.3 | length 2935.9
  Top Layer w40: C6.2@434.67,1200.1 C6.2@443.04,1191.73 ; C10.2@482.41,1424.55 594.08,1424.55 620.6,1398.03 D2.1@620.6,1387.15 ; v1(738.32,935.83) 780.95,978.46 780.95,1043.31 ; 738.32,1004.72 742.36,1004.72 780.95,1043.31 ; J1.3@758.63,1484 780.95,1461.68 780.95,1043.31
  Top Layer w50: C6.2@426.31,1191.73 431.33,1196.75 R4.1@431.33,1278.35 ; T1.5@510.26,859.84 510.26,888.29 ; 510.26,888.29 v1(482.41,916.14) v1(531.62,916.14) 510.26,894.78 510.26,888.29
  Top Layer w55: 285.56,992.91 v1(285.56,935.83) v1(285.56,886.61) 285.56,857.09 ; 334.77,989.78 v1(334.77,935.83) v1(334.77,886.61) 334.77,859.84 332.02,857.09 285.56,857.09 ; C4.2@364.3,1023.78 v1@256.03,1023.78 ; C6.2@426.31,1191.73 263.12,1191.73 256.03,1184.65 v1@256.03,1023.78 ; v1@256.03,1023.78 256.03,876.77 275.72,857.09 285.56,857.09 ; 689.1,866.93 v1(689.1,886.61) v1(689.1,935.83) 689.1,1004.72 738.32,1004.72 v1(738.32,935.83) v1(738.32,886.61) 738.32,869.69 725.72,857.09 698.94,857.09 689.1,866.93
  Bottom Layer w70: v1(738.32,935.83) 767.84,965.35 767.84,1474.79 J1.3@758.63,1484
  other v1: 256.03,1034.25 256.03,1083.46 559.18,1492.02 610.76,1492.02
-4V_2: C4_1.2 C5_1.2 C6_1.2 C7_1.2 C10_1.2 D2_1.1 J1_1.3 R4_1.1 T1_1.5 U2_1.3 | length 2935.9
  Top Layer w40: C6_1.2@1194.67,1200.1 C6_1.2@1203.04,1191.73 ; C10_1.2@1242.41,1424.55 1354.08,1424.55 1380.6,1398.03 D2_1.1@1380.6,1387.15 ; v1(1498.32,935.83) 1540.95,978.46 1540.95,1043.31 ; 1498.32,1004.72 1502.36,1004.72 1540.95,1043.31 ; J1_1.3@1518.63,1484 1540.95,1461.68 1540.95,1043.31
  Top Layer w50: C6_1.2@1186.31,1191.73 1191.33,1196.75 R4_1.1@1191.33,1278.35 ; T1_1.5@1270.26,859.84 1270.26,888.29 ; 1270.26,888.29 1270.26,894.78 v1(1291.62,916.14) v1(1242.41,916.14) 1270.26,888.29
  Top Layer w55: 1045.56,992.91 v1(1045.56,935.83) v1(1045.56,886.61) 1045.56,857.09 ; 1094.77,989.78 v1(1094.77,935.83) v1(1094.77,886.61) 1094.77,859.84 1092.02,857.09 1045.56,857.09 ; C4_1.2@1124.3,1023.78 v1@1016.03,1023.78 ; C6_1.2@1186.31,1191.73 1023.12,1191.73 1016.03,1184.65 v1@1016.03,1023.78 ; v1@1016.03,1023.78 1016.03,876.77 1035.72,857.09 1045.56,857.09 ; 1449.1,866.93 1458.94,857.09 1485.72,857.09 1498.32,869.69 v1(1498.32,886.61) v1(1498.32,935.83) 1498.32,1004.72 1449.1,1004.72 v1(1449.1,935.83) v1(1449.1,886.61) 1449.1,866.93
  Bottom Layer w70: v1(1498.32,935.83) 1527.84,965.35 1527.84,1474.79 J1_1.3@1518.63,1484
  other v1: 1016.03,1034.25 1016.03,1083.46 1319.18,1492.02 1370.76,1492.02
-4V_3: C4_2.2 C5_2.2 C6_2.2 C7_2.2 C10_2.2 D2_2.1 J1_2.3 R4_2.1 T1_2.5 U2_2.3 | length 2935.9
  Top Layer w40: C6_2.2@1954.67,1200.1 C6_2.2@1963.04,1191.73 ; C10_2.2@2002.41,1424.55 2114.08,1424.55 2140.6,1398.03 D2_2.1@2140.6,1387.15 ; v1(2258.32,935.83) 2300.95,978.46 2300.95,1043.31 ; 2258.32,1004.72 2262.36,1004.72 2300.95,1043.31 ; J1_2.3@2278.63,1484 2300.95,1461.68 2300.95,1043.31
  Top Layer w50: C6_2.2@1946.31,1191.73 1951.33,1196.75 R4_2.1@1951.33,1278.35 ; T1_2.5@2030.26,859.84 2030.26,888.29 ; 2030.26,888.29 2030.26,894.78 v1(2051.62,916.14) v1(2002.41,916.14) 2030.26,888.29
  Top Layer w55: 1805.56,992.91 v1(1805.56,935.83) v1(1805.56,886.61) 1805.56,857.09 ; 1854.77,989.78 v1(1854.77,935.83) v1(1854.77,886.61) 1854.77,859.84 1852.02,857.09 1805.56,857.09 ; C4_2.2@1884.3,1023.78 v1@1776.03,1023.78 ; C6_2.2@1946.31,1191.73 1783.12,1191.73 1776.03,1184.65 v1@1776.03,1023.78 ; v1@1776.03,1023.78 1776.03,876.77 1795.72,857.09 1805.56,857.09 ; 2209.1,866.93 2218.94,857.09 2245.72,857.09 2258.32,869.69 v1(2258.32,886.61) v1(2258.32,935.83) 2258.32,1004.72 2209.1,1004.72 v1(2209.1,935.83) v1(2209.1,886.61) 2209.1,866.93
  Bottom Layer w70: v1(2258.32,935.83) 2287.84,965.35 2287.84,1474.79 J1_2.3@2278.63,1484
  other v1: 1776.03,1034.25 1776.03,1083.46 2079.18,1492.02 2130.76,1492.02
-4V_4: C4_3.2 C5_3.2 C6_3.2 C7_3.2 C10_3.2 D2_3.1 J1_3.3 R4_3.1 T1_3.5 U2_3.3 | length 2935.9
  Top Layer w40: C6_3.2@2714.67,1200.1 C6_3.2@2723.04,1191.73 ; C10_3.2@2762.41,1424.55 2874.08,1424.55 2900.6,1398.03 D2_3.1@2900.6,1387.15 ; v1(3018.32,935.83) 3060.95,978.46 3060.95,1043.31 ; 3018.32,1004.72 3022.36,1004.72 3060.95,1043.31 ; J1_3.3@3038.63,1484 3060.95,1461.68 3060.95,1043.31
  Top Layer w50: C6_3.2@2706.31,1191.73 2711.33,1196.75 R4_3.1@2711.33,1278.35 ; T1_3.5@2790.26,859.84 2790.26,888.29 ; 2790.26,888.29 2790.26,894.78 v1(2811.62,916.14) v1(2762.41,916.14) 2790.26,888.29
  Top Layer w55: 2565.56,992.91 v1(2565.56,935.83) v1(2565.56,886.61) 2565.56,857.09 ; 2614.77,989.78 v1(2614.77,935.83) v1(2614.77,886.61) 2614.77,859.84 2612.02,857.09 2565.56,857.09 ; C4_3.2@2644.3,1023.78 v1@2536.03,1023.78 ; C6_3.2@2706.31,1191.73 2543.12,1191.73 2536.03,1184.65 v1@2536.03,1023.78 ; v1@2536.03,1023.78 2536.03,876.77 2555.72,857.09 2565.56,857.09 ; 2969.1,866.93 2978.94,857.09 3005.72,857.09 3018.32,869.69 v1(3018.32,886.61) v1(3018.32,935.83) 3018.32,1004.72 2969.1,1004.72 v1(2969.1,935.83) v1(2969.1,886.61) 2969.1,866.93
  Bottom Layer w70: v1(3018.32,935.83) 3047.84,965.35 3047.84,1474.79 J1_3.3@3038.63,1484
  other v1: 2536.03,1034.25 2536.03,1083.46 2839.18,1492.02 2890.76,1492.02
-4V_5: C4_4.2 C5_4.2 C6_4.2 C7_4.2 C10_4.2 D2_4.1 J1_4.3 R4_4.1 T1_4.5 U2_4.3 | length 2935.9
  Top Layer w40: C6_4.2@3474.67,1200.1 C6_4.2@3483.04,1191.73 ; C10_4.2@3522.41,1424.55 3634.08,1424.55 3660.6,1398.03 D2_4.1@3660.6,1387.15 ; v1(3778.31,935.83) 3820.95,978.46 3820.95,1043.31 ; 3778.31,1004.72 3782.36,1004.72 3820.95,1043.31 ; J1_4.3@3798.63,1484 3820.95,1461.68 3820.95,1043.31
  Top Layer w50: C6_4.2@3466.31,1191.73 3471.33,1196.75 R4_4.1@3471.33,1278.35 ; T1_4.5@3550.26,859.84 3550.26,888.29 ; 3550.26,888.29 3550.26,894.78 v1(3571.62,916.14) v1(3522.41,916.14) 3550.26,888.29
  Top Layer w55: 3325.56,992.91 v1(3325.56,935.83) v1(3325.56,886.61) 3325.56,857.09 ; 3374.77,989.78 v1(3374.77,935.83) v1(3374.77,886.61) 3374.77,859.84 3372.02,857.09 3325.56,857.09 ; C4_4.2@3404.3,1023.78 v1@3296.03,1023.78 ; C6_4.2@3466.31,1191.73 3303.12,1191.73 3296.03,1184.65 v1@3296.03,1023.78 ; v1@3296.03,1023.78 3296.03,876.77 3315.72,857.09 3325.56,857.09 ; 3729.1,866.93 3738.94,857.09 3765.72,857.09 3778.31,869.69 v1(3778.31,886.61) v1(3778.31,935.83) 3778.31,1004.72 3729.1,1004.72 v1(3729.1,935.83) v1(3729.1,886.61) 3729.1,866.93
  Bottom Layer w70: v1(3778.31,935.83) 3807.84,965.35 3807.84,1474.79 J1_4.3@3798.63,1484
  other v1: 3296.03,1034.25 3296.03,1083.46 3599.18,1492.02 3650.76,1492.02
